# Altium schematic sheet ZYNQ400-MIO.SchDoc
size A3
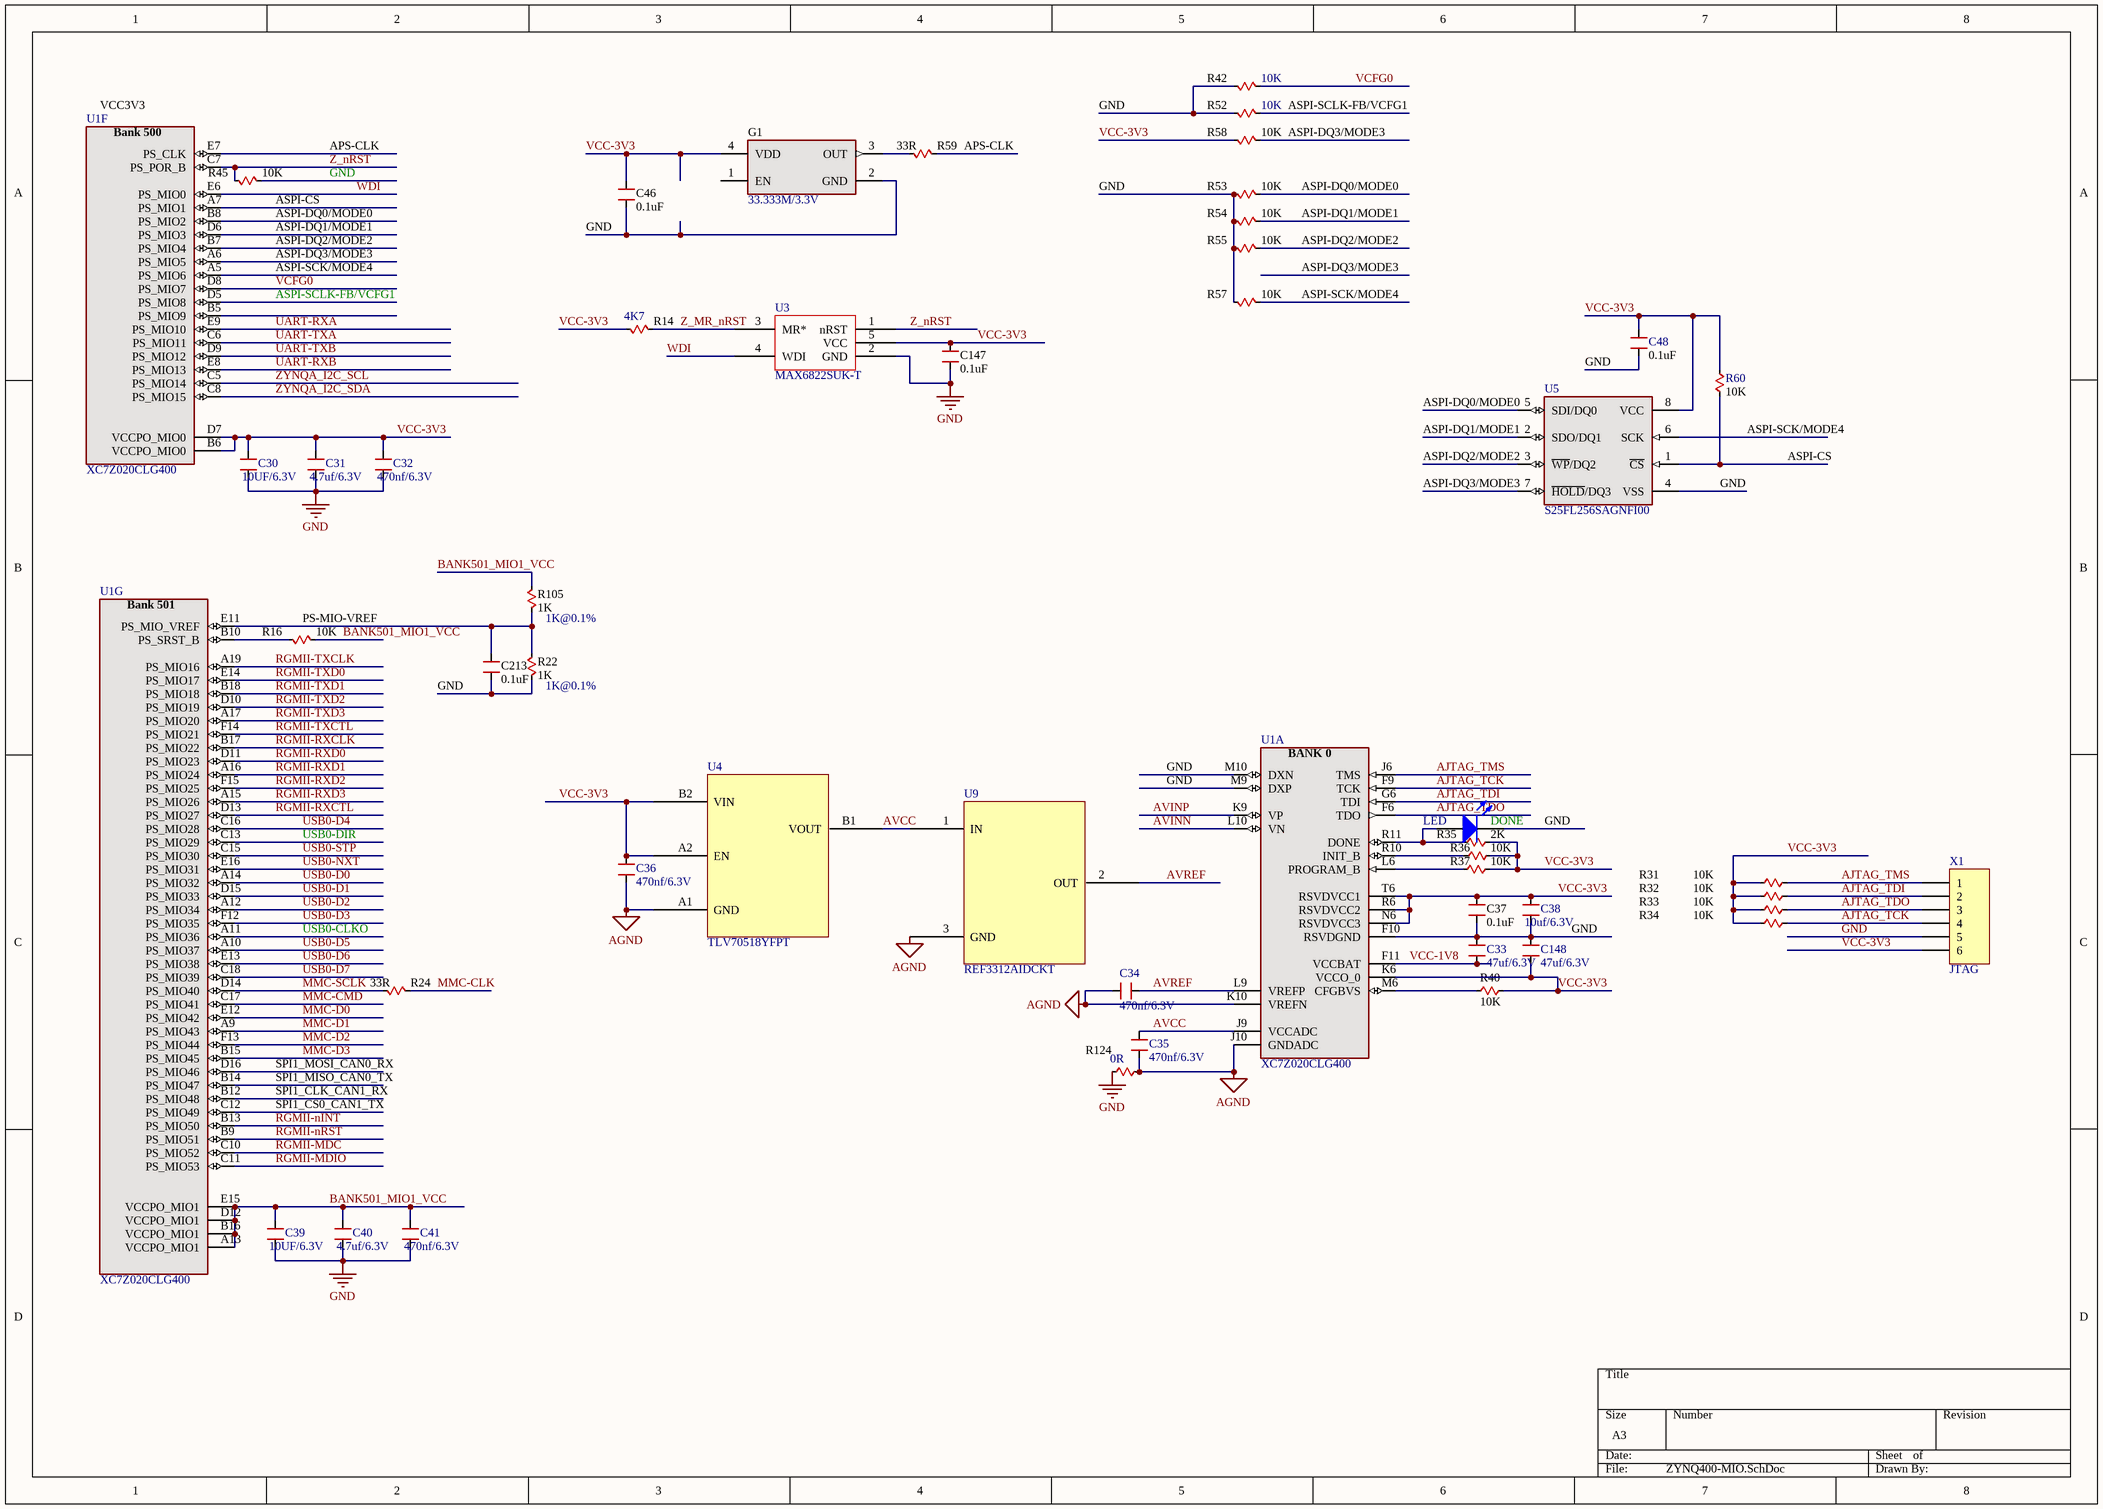
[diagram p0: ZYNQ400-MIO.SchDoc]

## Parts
C30  10UF/6.3V  [0402]
C31  4.7uf/6.3V  [0402]
C32  470nf/6.3V  [0402]
C33  47uf/6.3V  [0402]
C34  470nf/6.3V  [0402]
C35  470nf/6.3V  [0402]
C36  470nf/6.3V  [0402]
C37  0.1UF  [0402]
C38  10uf/6.3V  [0603]
C39  10UF/6.3V  [0402]
C40  4.7uf/6.3V  [0402]
C41  470nf/6.3V  [0402]
C46  0.1UF  [0402]
C48  0.1UF  [0402]
C147  0.1UF  [0402]
C148  47uf/6.3V  [0402]
C213  0.1uF  [0402]
DONE  LED  [D0402]
G1  33.333M/3.3V  [3.2*2.5]
R14  4K7  [0402]
R16  10K  [0402]
R22  1K@0.1%  value 1K  [0402]
R24  33R  [0402]
R31  10K  [0402]
R32  10K  [0402]
R33  10K  [0402]
R34  10K  [0402]
R35  value 2K  [0402]  (hidden comment: 1K)
R36  10K  [0402]
R37  10K  [0402]
R40  10K  [0402]
R42  10K  [0402]
R45  10K  [0402]
R52  10K  [0402]
R53  10K  [0402]
R54  10K  [0402]
R55  10K  [0402]
R57  10K  [0402]
R58  10K  [0402]
R59  33R  [0402]
R60  10K  [0402]
R105  1K@0.1%  value 1K  [0402]
R124  0R  [0402]
U1  XC7Z020CLG400  [CLG400]  (parts A,F,G of 9)
U3  MAX6822SUK-T  [MAX6822SUK]
U4  TLV70518YFPT  [WCSP-4]
U5  S25FL256SAGNFI00  [MLP8]
U9  REF3312AIDCKT  [SOT323]
X1  JTAG  [1.27*6]

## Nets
AGND: C34.1 C35.2 C36.1 R124.2 U1.J10(GNDADC) U1.K10(VREFN) U4.A1(GND) U9.3(GND)
GND: C30.2 C31.2 C32.2 C33.2 C37.2 C38.2 C39.2 C40.2 C41.2 C46.2 C48.2 C147.2 C148.2 C213.2 DONE.2(K) G1.2(GND) R22.2 R42.1 R45.2 R52.1 R53.1 R54.1 R55.1 R57.1 R124.1 U1.F10(RSVDGND) U1.M9(DXP) U1.M10(DXN) U3.2(GND) U5.4(VSS) X1.5
AJTAG_TCK: R34.2 U1.F9(TCK) X1.4
AJTAG_TDI: R32.2 U1.G6(TDI) X1.2
AJTAG_TDO: R33.2 U1.F6(TDO) X1.3
AJTAG_TMS: R31.2 U1.J6(TMS) X1.1
APS-CLK: R59.2 U1.E7(PS_CLK)
ASPI-CS: R60.2 U1.A7(PS_MIO1) U5.1(~{CS})
ASPI-DQ0/MODE0: R53.2 U1.B8(PS_MIO2) U5.5(SDI/DQ0)
ASPI-DQ1/MODE1: R54.2 U1.D6(PS_MIO3) U5.2(SDO/DQ1)
ASPI-DQ2/MODE2: R55.2 U1.B7(PS_MIO4) U5.3(~{WP}/DQ2)
ASPI-DQ3/MODE3: R58.2 U1.A6(PS_MIO5) U5.7(~{HOLD}/DQ3)
ASPI-SCK/MODE4: R57.2 U1.A5(PS_MIO6) U5.6(SCK)
ASPI-SCLK-FB/VCFG1: R52.2 U1.D5(PS_MIO8)
AVCC: C35.1 U1.J9(VCCADC) U4.B1(VOUT) U9.1(IN)
AVINN: U1.L10(VN)
AVINP: U1.K9(VP)
AVREF: C34.2 U1.L9(VREFP) U9.2(OUT)
BANK501_MIO1_VCC: C39.1 C40.1 C41.1 R16.2 R105.1 U1.A13(VCCPO_MIO1) U1.B16(VCCPO_MIO1) U1.D12(VCCPO_MIO1) U1.E15(VCCPO_MIO1)
MMC-CLK: R24.2
MMC-CMD: U1.C17(PS_MIO41)
MMC-D0: U1.E12(PS_MIO42)
MMC-D1: U1.A9(PS_MIO43)
MMC-D2: U1.F13(PS_MIO44)
MMC-D3: U1.B15(PS_MIO45)
MMC-SCLK: R24.1 U1.D14(PS_MIO40)
PS-MIO-VREF: C213.1 R22.1 R105.2 U1.E11(PS_MIO_VREF)
RGMII-MDC: U1.C10(PS_MIO52)
RGMII-MDIO: U1.C11(PS_MIO53)
RGMII-nINT: U1.B13(PS_MIO50)
RGMII-nRST: U1.B9(PS_MIO51)
RGMII-RXCLK: U1.B17(PS_MIO22)
RGMII-RXCTL: U1.D13(PS_MIO27)
RGMII-RXD0: U1.D11(PS_MIO23)
RGMII-RXD1: U1.A16(PS_MIO24)
RGMII-RXD2: U1.F15(PS_MIO25)
RGMII-RXD3: U1.A15(PS_MIO26)
RGMII-TXCLK: U1.A19(PS_MIO16)
RGMII-TXCTL: U1.F14(PS_MIO21)
RGMII-TXD0: U1.E14(PS_MIO17)
RGMII-TXD1: U1.B18(PS_MIO18)
RGMII-TXD2: U1.D10(PS_MIO19)
RGMII-TXD3: U1.A17(PS_MIO20)
SPI1_CLK_CAN1_RX: U1.B12(PS_MIO48)
SPI1_CS0_CAN1_TX: U1.C12(PS_MIO49)
SPI1_MISO_CAN0_TX: U1.B14(PS_MIO47)
SPI1_MOSI_CAN0_RX: U1.D16(PS_MIO46)
UART-RXA: U1.E9(PS_MIO10)
UART-RXB: U1.E8(PS_MIO13)
UART-TXA: U1.C6(PS_MIO11)
UART-TXB: U1.D9(PS_MIO12)
USB0-CLKO: U1.A11(PS_MIO36)
USB0-D0: U1.A14(PS_MIO32)
USB0-D1: U1.D15(PS_MIO33)
USB0-D2: U1.A12(PS_MIO34)
USB0-D3: U1.F12(PS_MIO35)
USB0-D4: U1.C16(PS_MIO28)
USB0-D5: U1.A10(PS_MIO37)
USB0-D6: U1.E13(PS_MIO38)
USB0-D7: U1.C18(PS_MIO39)
USB0-DIR: U1.C13(PS_MIO29)
USB0-NXT: U1.E16(PS_MIO31)
USB0-STP: U1.C15(PS_MIO30)
VCC-1V8: C33.1 U1.F11(VCCBAT)
VCC-3V3: C30.1 C31.1 C32.1 C36.2 C37.1 C38.1 C46.1 C48.1 C147.1 C148.1 G1.4(VDD) R14.1 R31.1 R32.1 R33.1 R34.1 R35.2 R36.1 R37.2 R40.2 R58.1 R60.1 U1.B6(VCCPO_MIO0) U1.D7(VCCPO_MIO0) U1.K6(VCCO_0) U1.N6(RSVDVCC3) U1.R6(RSVDVCC2) U1.T6(RSVDVCC1) U3.5(VCC) U4.A2(EN) U4.B2(VIN) U5.8(VCC) X1.6
VCFG0: R42.2 U1.D8(PS_MIO7)
WDI: U1.E6(PS_MIO0) U3.4(WDI)
Z_MR_nRST: R14.2 U3.3(MR*)
Z_nRST: R45.1 U1.C7(PS_POR_B) U3.1(nRST)
ZYNQA_I2C_SCL: U1.C5(PS_MIO14)
ZYNQA_I2C_SDA: U1.C8(PS_MIO15)
NetDONE_1: DONE.1(A) R35.1 U1.R11(DONE)
NetG1_3: G1.3(OUT) R59.1
NetR16_1: R16.1 U1.B10(PS_SRST_B)
NetR36_2: R36.2 U1.R10(INIT_B)
NetR37_1: R37.1 U1.L6(PROGRAM_B)
NetR40_1: R40.1 U1.M6(CFGBVS)

Not connected (* = marked no-connect by the designer): G1 1(EN); U1 B5(PS_MIO9)

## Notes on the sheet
- VCC3V3

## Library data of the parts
C30-C41 C46 C48 C147 C148 C213 = CAPACITOR: Generic Capacitor
DONE = LED0: Typical INFRARED GaAs LED
G1 = FXO-HC5: 3.3V HCMOS Oscillator; Manufacturer: Fox Electronics; Value: 33.33MHz
R14 = RESISTOR: Generic Resistor; Value: 33R
R16 R22 R24 R31-R37 R40 R42 R45 R52-R55 R57-R60 R105 = RESISTOR: Generic Resistor
R124 = RESISTOR: Generic Resistor; Value: 10K
U1 = XC7Z020-CLG400: Zynq 7000 FPGA 20 Die, in a CSG 484 Package; Manufacturer: Xilinx
U5 = N25Q12-F8: Serial Flash Memory, 16Mbit, Low Voltage, 50MHz SPI Bus Interface; Manufacturer: Spansion
X1 = Header 6: Header, 6-Pin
